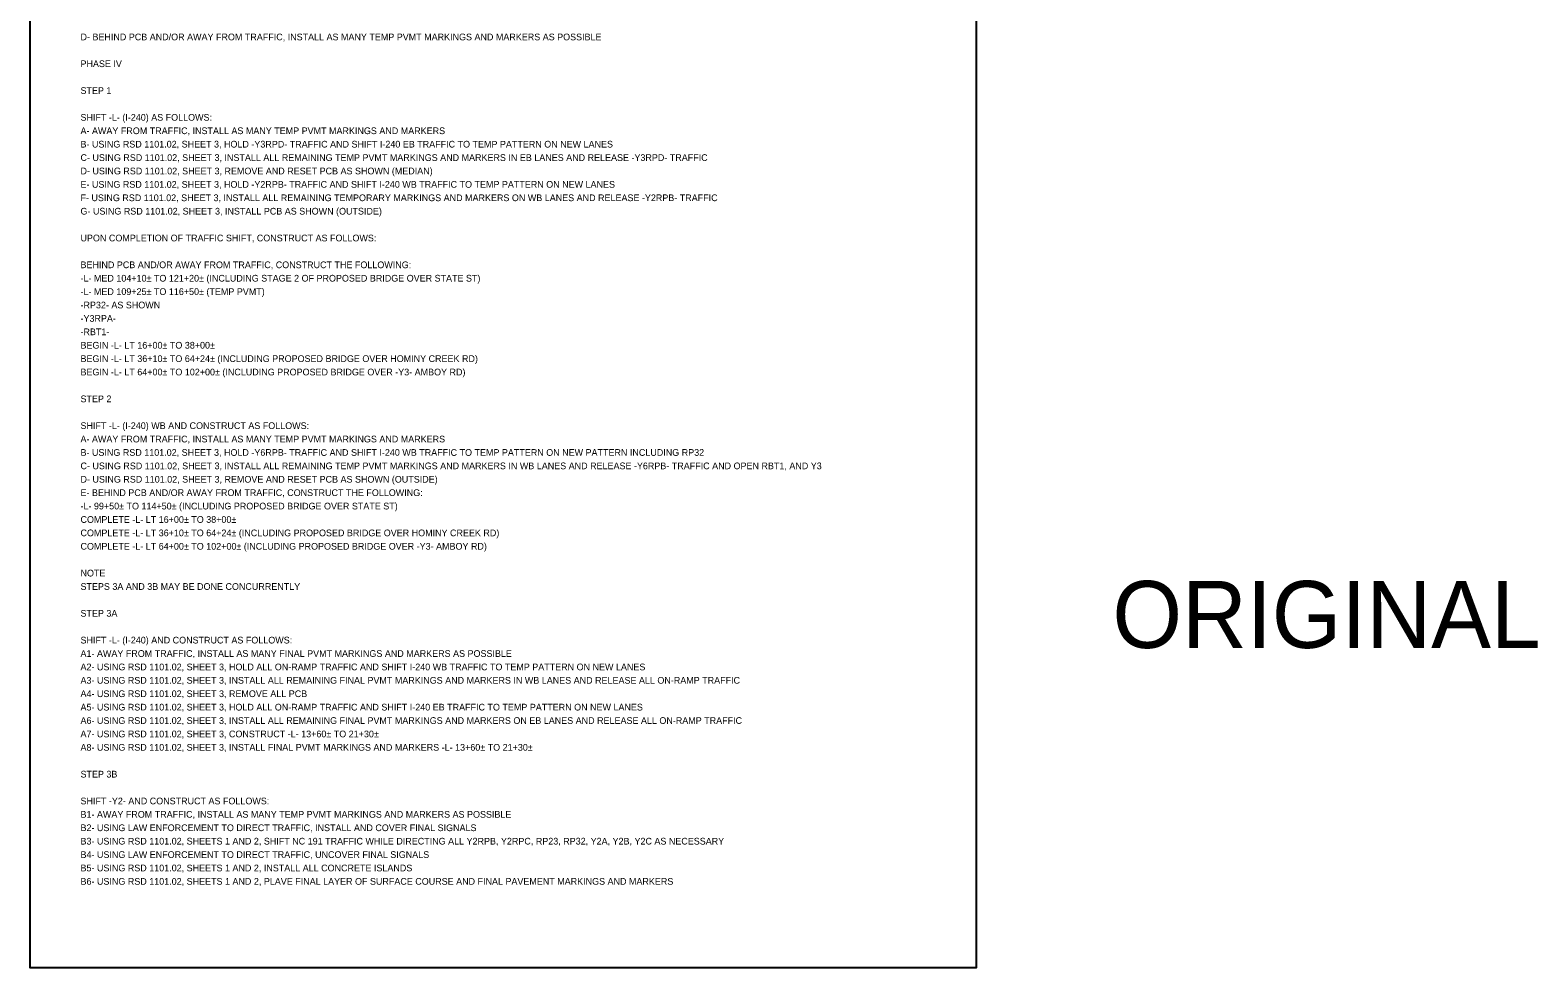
# Model space of a CAD drawing. Extents: x 2483905 to 2494512, y 366160 to 372330.
# Drawn here: x 2484419 to 2485994, y 366160 to 367139 of the extents above; entities that cross this region are included whole.
import ezdxf

# ---------------------------------------------------------------- set-up
doc = ezdxf.new("R2010")
doc.units = 0
doc.layers.add('Scratch_Level_6', color=7, linetype='Continuous')

msp = doc.modelspace()

# ---------------------------------------------------------------- linework, layer by layer
at = {"layer": 'Scratch_Level_6'}
msp.add_lwpolyline([(2484419.4, 370066.6), (2485407.1, 370066.6), (2485407.1, 366159.7), (2484419.4, 366159.7)], close=True, dxfattribs=at)

# ---------------------------------------------------------------- texts
for s, height, p in [('D- BEHIND PCB AND/OR AWAY FROM TRAFFIC, INSTALL AS MANY TEMP PVMT MARKINGS AND MARKERS AS POSSIBLE', 7, (2484472, 367128.5)), ('PHASE IV', 7, (2484472, 367100.5)), ('STEP 1', 7, (2484472, 367072.5)), ('SHIFT -L- (I-240) AS FOLLOWS:', 7, (2484472, 367044.5)), ('A- AWAY FROM TRAFFIC, INSTALL AS MANY TEMP PVMT MARKINGS AND MARKERS', 7, (2484472, 367030.5)), ('B- USING RSD 1101.02, SHEET 3, HOLD -Y3RPD- TRAFFIC AND SHIFT I-240 EB TRAFFIC TO TEMP PATTERN ON NEW LANES', 7, (2484472, 367016.5)), ('C- USING RSD 1101.02, SHEET 3, INSTALL ALL REMAINING TEMP PVMT MARKINGS AND MARKERS IN EB LANES AND RELEASE -Y3RPD- TRAFFIC', 7, (2484472, 367002.5)), ('D- USING RSD 1101.02, SHEET 3, REMOVE AND RESET PCB AS SHOWN (MEDIAN)', 7, (2484472, 366988.5)), ('E- USING RSD 1101.02, SHEET 3, HOLD -Y2RPB- TRAFFIC AND SHIFT I-240 WB TRAFFIC TO TEMP PATTERN ON NEW LANES', 7, (2484472, 366974.5)), ('F- USING RSD 1101.02, SHEET 3, INSTALL ALL REMAINING TEMPORARY MARKINGS AND MARKERS ON WB LANES AND RELEASE -Y2RPB- TRAFFIC', 7, (2484472, 366960.5)), ('G- USING RSD 1101.02, SHEET 3, INSTALL PCB AS SHOWN (OUTSIDE)', 7, (2484472, 366946.5)), ('UPON COMPLETION OF TRAFFIC SHIFT, CONSTRUCT AS FOLLOWS:', 7, (2484472, 366918.5)), ('BEHIND PCB AND/OR AWAY FROM TRAFFIC, CONSTRUCT THE FOLLOWING:', 7, (2484472, 366890.5)), ('-L- MED 104+10± TO 121+20± (INCLUDING STAGE 2 OF PROPOSED BRIDGE OVER STATE ST)', 7, (2484472, 366876.5)), ('-L- MED 109+25± TO 116+50± (TEMP PVMT)', 7, (2484472, 366862.5)), ('-RP32- AS SHOWN', 7, (2484472, 366848.5)), ('-Y3RPA-', 7, (2484472, 366834.5)), ('-RBT1-', 7, (2484472, 366820.5)), ('BEGIN -L- LT 16+00± TO 38+00±', 7, (2484472, 366806.5)), ('BEGIN -L- LT 36+10± TO 64+24± (INCLUDING PROPOSED BRIDGE OVER HOMINY CREEK RD)', 7, (2484472, 366792.5)), ('BEGIN -L- LT 64+00± TO 102+00± (INCLUDING PROPOSED BRIDGE OVER -Y3- AMBOY RD)', 7, (2484472, 366778.5)), ('STEP 2', 7, (2484472, 366750.5)), ('SHIFT -L- (I-240) WB AND CONSTRUCT AS FOLLOWS:', 7, (2484472, 366722.5)), ('A- AWAY FROM TRAFFIC, INSTALL AS MANY TEMP PVMT MARKINGS AND MARKERS', 7, (2484472, 366708.5)), ('B- USING RSD 1101.02, SHEET 3, HOLD -Y6RPB- TRAFFIC AND SHIFT I-240 WB TRAFFIC TO TEMP PATTERN ON NEW PATTERN INCLUDING RP32', 7, (2484472, 366694.5)), ('C- USING RSD 1101.02, SHEET 3, INSTALL ALL REMAINING TEMP PVMT MARKINGS AND MARKERS IN WB LANES AND RELEASE -Y6RPB- TRAFFIC AND OPEN RBT1, AND Y3', 7, (2484472, 366680.5)), ('D- USING RSD 1101.02, SHEET 3, REMOVE AND RESET PCB AS SHOWN (OUTSIDE)', 7, (2484472, 366666.5)), ('-L- 99+50± TO 114+50± (INCLUDING PROPOSED BRIDGE OVER STATE ST)', 7, (2484472, 366638.5)), ('E- BEHIND PCB AND/OR AWAY FROM TRAFFIC, CONSTRUCT THE FOLLOWING:', 7, (2484472, 366652.5)), ('COMPLETE -L- LT 16+00± TO 38+00±', 7, (2484472, 366624.5)), ('COMPLETE -L- LT 36+10± TO 64+24± (INCLUDING PROPOSED BRIDGE OVER HOMINY CREEK RD)', 7, (2484472, 366610.5)), ('COMPLETE -L- LT 64+00± TO 102+00± (INCLUDING PROPOSED BRIDGE OVER -Y3- AMBOY RD)', 7, (2484472, 366596.5)), ('NOTE', 7, (2484472, 366568.5)), ('STEPS 3A AND 3B MAY BE DONE CONCURRENTLY', 7, (2484472, 366554.5)), ('ORIGINAL', 70, (2485549.5, 366493.8)), ('STEP 3A', 7, (2484472, 366526.5)), ('SHIFT -L- (I-240) AND CONSTRUCT AS FOLLOWS:', 7, (2484472, 366498.5)), ('A1- AWAY FROM TRAFFIC, INSTALL AS MANY FINAL PVMT MARKINGS AND MARKERS AS POSSIBLE', 7, (2484472, 366484.5)), ('A2- USING RSD 1101.02, SHEET 3, HOLD ALL ON-RAMP TRAFFIC AND SHIFT I-240 WB TRAFFIC TO TEMP PATTERN ON NEW LANES', 7, (2484472, 366470.5)), ('A3- USING RSD 1101.02, SHEET 3, INSTALL ALL REMAINING FINAL PVMT MARKINGS AND MARKERS IN WB LANES AND RELEASE ALL ON-RAMP TRAFFIC', 7, (2484472, 366456.5)), ('A4- USING RSD 1101.02, SHEET 3, REMOVE ALL PCB', 7, (2484472, 366442.5)), ('A5- USING RSD 1101.02, SHEET 3, HOLD ALL ON-RAMP TRAFFIC AND SHIFT I-240 EB TRAFFIC TO TEMP PATTERN ON NEW LANES', 7, (2484472, 366428.5)), ('A6- USING RSD 1101.02, SHEET 3, INSTALL ALL REMAINING FINAL PVMT MARKINGS AND MARKERS ON EB LANES AND RELEASE ALL ON-RAMP TRAFFIC', 7, (2484472, 366414.5)), ('A7- USING RSD 1101.02, SHEET 3, CONSTRUCT -L- 13+60± TO 21+30±', 7, (2484472, 366400.5)), ('A8- USING RSD 1101.02, SHEET 3, INSTALL FINAL PVMT MARKINGS AND MARKERS -L- 13+60± TO 21+30±', 7, (2484472, 366386.5)), ('STEP 3B', 7, (2484472, 366358.5)), ('SHIFT -Y2- AND CONSTRUCT AS FOLLOWS:', 7, (2484472, 366330.5)), ('B1- AWAY FROM TRAFFIC, INSTALL AS MANY TEMP PVMT MARKINGS AND MARKERS AS POSSIBLE', 7, (2484472, 366316.5)), ('B2- USING LAW ENFORCEMENT TO DIRECT TRAFFIC, INSTALL AND COVER FINAL SIGNALS', 7, (2484472, 366302.5)), ('B3- USING RSD 1101.02, SHEETS 1 AND 2, SHIFT NC 191 TRAFFIC WHILE DIRECTING ALL Y2RPB, Y2RPC, RP23, RP32, Y2A, Y2B, Y2C AS NECESSARY', 7, (2484472, 366288.5)), ('B4- USING LAW ENFORCEMENT TO DIRECT TRAFFIC, UNCOVER FINAL SIGNALS', 7, (2484472, 366274.5)), ('B5- USING RSD 1101.02, SHEETS 1 AND 2, INSTALL ALL CONCRETE ISLANDS', 7, (2484472, 366260.5)), ('B6- USING RSD 1101.02, SHEETS 1 AND 2, PLAVE FINAL LAYER OF SURFACE COURSE AND FINAL PAVEMENT MARKINGS AND MARKERS', 7, (2484472, 366246.5))]:
    msp.add_text(s, height=height, dxfattribs=at).set_placement(p)

doc.saveas('drawing.dxf')
